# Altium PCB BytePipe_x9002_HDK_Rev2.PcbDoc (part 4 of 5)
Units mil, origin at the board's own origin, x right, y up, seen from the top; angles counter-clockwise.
Board outline 4250 x 4250 mil, 8 copper layers (Top Layer, L2-GND, L3-SIG, L4-GND, L5-PWR, L6-SIG, L7-GND, Bottom Layer), stack 63 mil thick; 296 components, 250 nets, 1198 pads, 2326 vias.
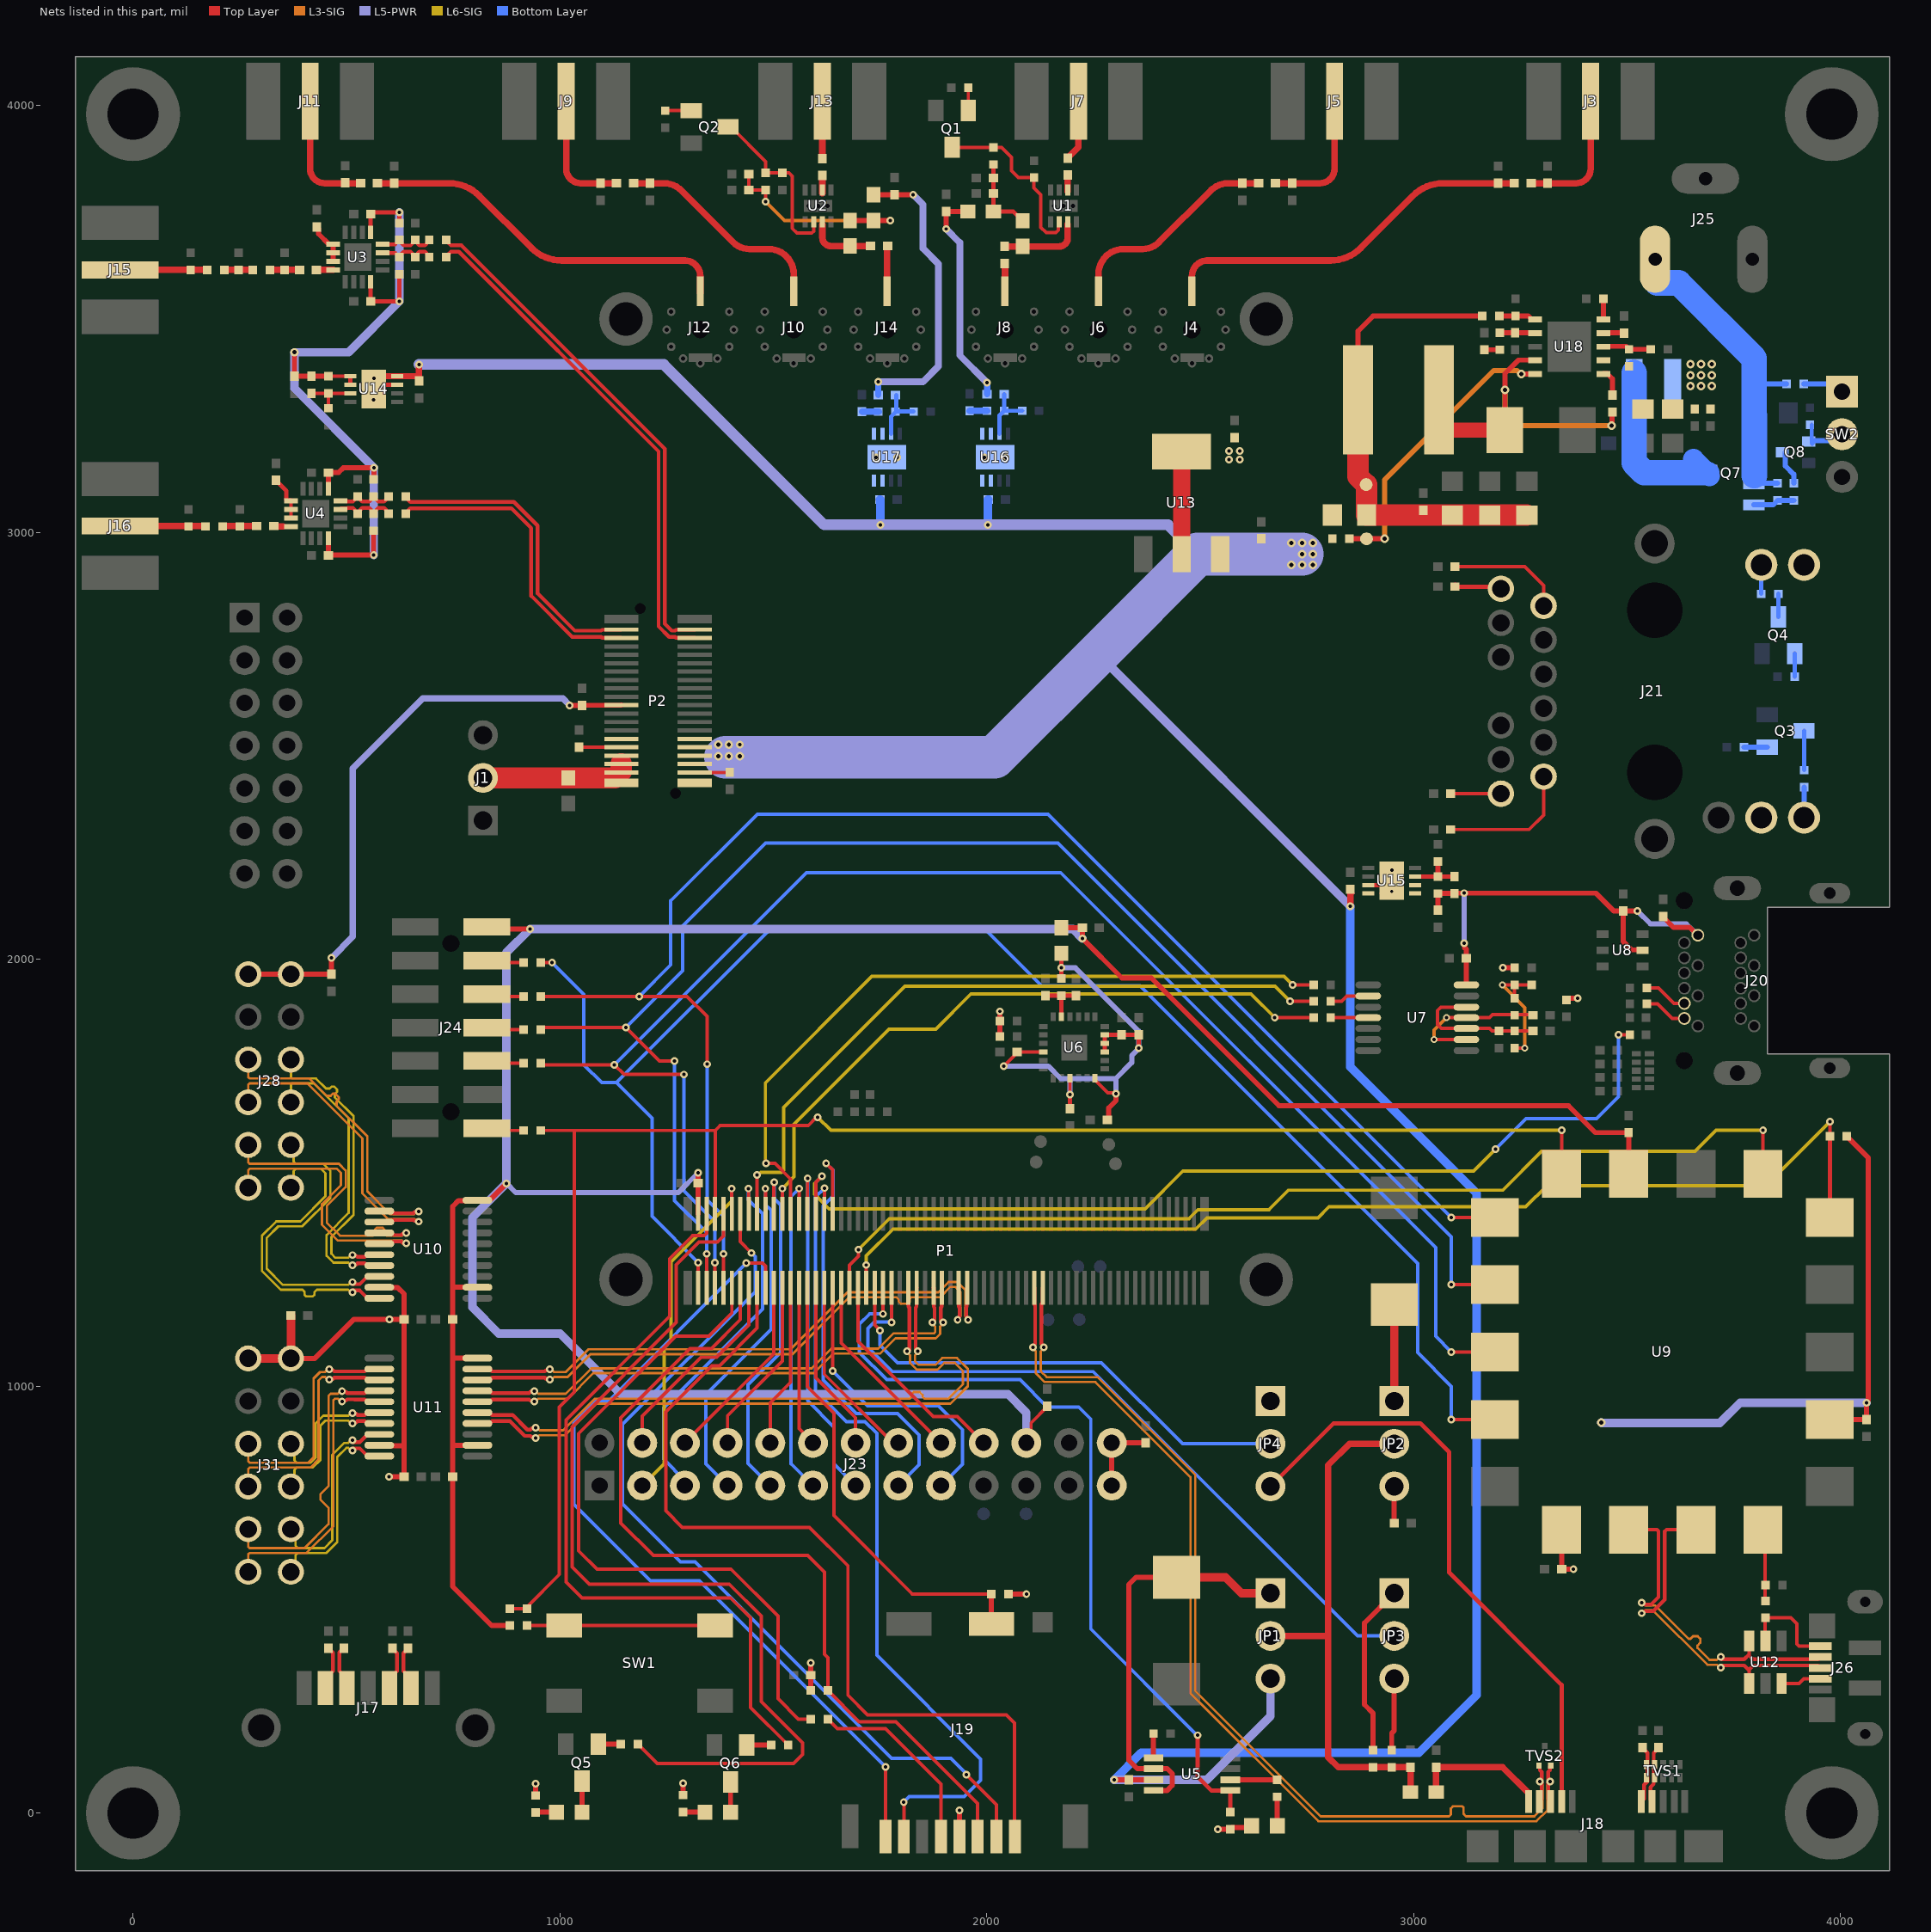
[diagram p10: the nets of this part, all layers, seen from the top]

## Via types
v1: diameter 18, hole 8, Top Layer to Bottom Layer, tented both sides, 2283 vias
v2: diameter 20, hole 10, Top Layer to Bottom Layer, tented both sides, 39 vias
v3: diameter 16, hole 8, Top Layer to Bottom Layer, tented both sides, 4 vias

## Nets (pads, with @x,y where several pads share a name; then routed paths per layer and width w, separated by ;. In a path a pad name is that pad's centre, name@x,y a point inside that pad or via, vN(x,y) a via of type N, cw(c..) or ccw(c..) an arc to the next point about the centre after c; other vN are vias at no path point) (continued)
IO_L10_N: P1.70 U11.5 | length 1574.6
  Top Layer w8.75: U11.5@807,938 835.96,938 841.34,932.62 889.45,932.62 923.86,898.21 931.31,898.21 934.16,901.07 941.45,901.07 v1(943.22,902.84) ; P1.70@1816.42,1230.39 1817.04,1229.76 1817.04,1185.88 1818.88,1184.04 v1@1818.88,1084.9
  L3-SIG w5.5: v1(943.22,902.84) 946.44,902.84 952.69,896.59 964.42,896.59 1007.94,896.59 1081.85,970.51 1819.51,970.51 1823,974 1823,980 1829,986 1843,986 1850,979 1850,975 1854.49,970.51 1910.51,970.51 1944.5,1004.5 1944.5,1035.5 1925.5,1054.5 1900.76,1054.5 1884.76,1038.5 1836.24,1038.5 1820.48,1054.26 1820.48,1072.12 1813.73,1078.87 v1(1813.73,1081.59)
IO_L10_P: P1.68 U11.4 | length 1575.1
  Top Layer w8.75: U11.4@807,912.5 835.96,912.5 841.34,917.88 883.34,917.88 917.75,883.46 931.31,883.46 934.16,880.61 941.45,880.61 v1(943.22,878.84) ; v1@1833.63,1084.76 1833.63,1184.04 1835.48,1185.88 1835.48,1229.76 P1.68@1836.1,1230.39
  L3-SIG w5.5: v1(943.22,878.84) 946.44,878.84 952.69,885.09 969.19,885.09 1012.7,885.09 1086.62,959.01 1915.27,959.01 1956,999.74 1956,1040.26 1930.26,1066 1896,1066 1880,1050 1841,1050 1831.98,1059.02 1831.98,1072.12 1838.73,1078.87 v1(1838.73,1081.59)
IO_L11_N: P1.64 U11.7 | length 1243.7
  Top Layer w8.75: U11.7@807,989 835.96,989 841.34,983.62 856.81,983.62 ; 856.84,983.59 899.8,983.59 ; 899.84,983.56 928.09,983.56 930.94,986.41 938.23,986.41 v1(940,988.18) ; P1.64@1875.47,1230.39 1876.1,1229.76 1876.1,1185.88 1877.94,1184.04 v1@1877.94,1152.1
  L3-SIG w5.5: v1(940,988.18) 943.22,988.18 949.47,981.93 1013.99,981.93 1073.83,1041.77 1590.18,1041.77 1636.4,1088 1745.96,1088 1781.49,1123.53 1876.4,1123.53 1879.62,1126.75 1879.62,1139.51 1872.87,1146.26 v1(1872.87,1148.98)
IO_L11_P: P1.62 U11.6 | length 1262.8
  Top Layer w8.75: U11.6@807,963.5 835.96,963.5 841.34,968.88 850,968.88 850.07,968.81 856.81,968.81 ; 856.84,968.84 893.69,968.84 ; 893.73,968.81 928.09,968.81 930.94,965.95 938.23,965.95 v1(940,964.18) ; v1@1892.69,1152.1 1892.69,1184.04 1894.53,1185.88 1894.53,1229.76 P1.62@1895.16,1230.39
  L3-SIG w5.5: v1(940,964.18) 943.22,964.18 949.47,970.43 1018.75,970.43 1078.6,1030.27 1594.94,1030.27 1641.16,1076.5 1750.73,1076.5 1786.25,1112.03 1881.16,1112.03 1891.12,1121.99 1891.12,1139.51 1897.87,1146.26 v1(1897.87,1148.98)
IO_L12_N: P1.56 U11.9 | length 1395.6
  Top Layer w8.75: U11.9@807,1040 835.96,1040 841.34,1034.63 947.47,1034.63 964.98,1034.61 967.84,1037.47 975.13,1037.47 v1(976.9,1039.24) ; P1.56@1954.21,1230.39 1953.59,1229.76 1953.59,1185.88 1951.75,1184.04 1951.75,1163.04 1956.84,1157.95 v1(1956.84,1155.44)
  L3-SIG w5.5: v1(976.9,1039.24) 980.12,1039.24 986.37,1032.99 1013.55,1032.99 1066.91,1086.35 1540.37,1086.35 1674.01,1220 1886.74,1220 1910.74,1244 1931.26,1244 1950.09,1225.18 1950.09,1164.92 1956.84,1158.17 v1(1956.84,1155.44)
IO_L12_P: P1.58 U11.8 | length 1396.5
  Top Layer w8.75: U11.8@807,1014.5 835.96,1014.5 841.34,1019.88 941.36,1019.88 964.98,1019.86 967.84,1017.01 975.13,1017.01 v1(976.9,1015.24) ; v1(1931.84,1155.44) 1931.84,1157.95 1937,1163.1 1937,1184.04 1935.15,1185.88 1935.15,1229.76 P1.58@1934.53,1230.39
  L3-SIG w5.5: v1(976.9,1015.24) 980.12,1015.24 986.37,1021.49 1018.31,1021.49 1071.68,1074.85 1545.13,1074.85 1678.78,1208.5 1788.5,1208.5 1794,1203 1794,1198 1799,1193 1815,1193 1820,1198 1820,1205 1823.5,1208.5 1891.5,1208.5 1915.5,1232.5 1926.5,1232.5 1938.59,1220.41 1938.59,1164.92 1931.84,1158.17 v1(1931.84,1155.44)
MCS0_N: R6.2 R9.2 R13.1 U3.11 | length 139.4
  Top Layer w8.75: U3.11@585,3655 585.13,3654.87 614.12,3654.87 R6.2@624,3645 629.62,3650.62 629.63,3652.48 634.75,3657.61 650.25,3657.61 655.38,3652.48 655.38,3650.62 R13.1@661,3645 666.62,3650.62 666.62,3653.38 670.88,3657.62 684.12,3657.62 688.38,3653.38 688.38,3650.62 R9.2@694,3645
MCS0_P: R7.2 R8.2 R14.1 U3.12 | length 139.5
  Top Layer w8.75: U3.12@585,3675 U3.12@585,3675 614.12,3675.06 R7.2@624.03,3684.97 629.66,3679.34 629.66,3677.48 634.78,3672.36 650.23,3672.36 655.38,3677.5 655.38,3679.38 R14.1@661,3685 666.62,3679.38 666.62,3676.62 670.88,3672.38 684.12,3672.38 688.38,3676.62 688.38,3679.37 R8.2@694,3685
MCS_N: P2.06 R9.1 | length 1203.9
  Top Layer w8.75: R9.1@734,3645 739.63,3650.62 739.63,3652.5 744.75,3657.62 763.38,3657.62 1231.25,3189.75 1231.25,2779.89 1256.04,2755.11 1270.27,2755.11 1272.11,2753.26 1315.99,2753.26 P2.06@1316.61,2752.64
MCS_P: P2.04 R8.1 | length 1203.9
  Top Layer w8.75: R8.1@734,3685 739.62,3679.38 739.62,3677.5 744.75,3672.38 769.48,3672.38 1246,3195.86 1246,2786 1262.14,2769.86 1270.27,2769.86 1272.11,2771.7 1315.99,2771.7 P2.04@1316.61,2772.32
MIO26: J23.11 P1.95 | length 784
  Top Layer w8: P1.95@1560.44,1403.68 v1@1560.44,1462.93
  Bottom Layer w8: v1(1560.37,1463) 1542,1444.63 1542,818 J23.11@1593,767
MIO27: P1.105 R40.2 | length 1680.1
  Top Layer w8: P1.105@1461.54,1403.07 P1.105@1462.09,1403.61 1462.04,1403.66 1462.04,1494.96 v1(1462,1495) ; v1(2710.94,1902) R40.2@2766,1902
  L6-SIG w8: v1(1462,1495) 1464.71,1495 1470.71,1501 1519.31,1501 1524,1505.69 1524,1653 1808,1937 2675.94,1937 v1(2710.94,1902)
MIO28: P1.91 R49.1 | length 2322
  Top Layer w8: P1.91@1599.88,1403.61 P1.91@1599.88,1403.61 1599.94,1477.94 v1(1614,1492) ; v1(3480.67,1822.92) 3480.75,1823 R49.1@3507,1823
  L6-SIG w8: v1(1614,1492) 1597,1475 1597,1449 1630.7,1415.3 2371.16,1415.3 2459.52,1503.66 3140.9,1503.66 v1(3192.31,1555.07)
  Bottom Layer w8: v1(3192.31,1555.07) 3263.65,1626.41 3429.05,1626.41 3480.67,1678.04 v1(3480.67,1822.92)
MIO29: P1.97 R39.2 | length 1740.1
  Top Layer w8: v1(1483,1522) 1504,1522 1540.83,1485.17 P1.97@1540.83,1403.61 ; v1@2717.12,1939.88 R39.2@2765.88,1939.88
  Top Layer w10: v1(2717,1939.77) v1@2717.12,1939.88 ; R39.2@2765.88,1939.88 R39.2@2766,1940
  L6-SIG w8: v1(1483,1522) 1481.61,1523.39 1481.61,1710.72 1730.88,1960 2696.77,1960 v1(2717,1939.77)
MIO30: P1.99 R42.2 | length 1588.6
  Top Layer w8: v1(1521,1463) 1521.07,1462.93 1521.07,1403.68 P1.99@1521.14,1403.61 ; v1@2675.04,1862.99 R42.2@2766,1863
  L6-SIG w8: v1(1521,1463) 1549,1491 1549,1613.97 1771.52,1836.48 1880.48,1836.48 1963,1919 2619,1919 v1(2675.03,1862.97)
MIO31: J23.5 P1.107 | length 885.6
  Top Layer w8: P1.107@1442.33,1403.68 v1@1442.33,1462.93
  Bottom Layer w8: J23.5@1293,767 1293,779 1243,829 1243,949 1475,1181 1475,1404.04 1442.26,1436.78 v1(1442.26,1463)
MIO32: J23.3 P1.111 | length 842.2
  Top Layer w8: P1.111@1402.96,1403.68 v1@1402.96,1462.93
  L6-SIG w8: J23.3@1193,767 1244,818 1244,1090 1261,1107 1261,1291 1402.89,1432.89 v1(1402.89,1463)
MIO33: J23.13 P1.93 | length 849.9
  Top Layer w8: P1.93@1580.28,1403.7 v1@1580.28,1486.91
  Bottom Layer w8: v1(1580.37,1487) 1580.37,965.63 1642,904 1642,818 J23.13@1693,767
MIO34: J23.6 P1.102 | length 449.7
  Top Layer w8: J23.6@1293,867 1501.34,1075.34 1501.34,1230.27 P1.102@1501.46,1230.39
MIO35: J23.9 P1.101 | length 844.5
  Top Layer w8: P1.101@1501.54,1403.7 v1@1501.54,1478
  Bottom Layer w8: J23.9@1493,767 1441,819 1441,1003 1517,1079 1517,1424 1502,1439 v1(1502,1478)
MIO36: J23.7 P1.103 | length 845.3
  Top Layer w8: P1.103@1481.7,1403.68 v1@1481.7,1462.93
  Bottom Layer w8: J23.7@1393,767 1342,818 1342,980 1495,1133 1495,1412.21 1481.63,1425.58 v1(1481.63,1463)
MIO37: J23.15 P1.87 | length 1066.7
  Top Layer w8: v1(1623.65,1522.39) 1639.1,1506.93 1639.1,1403.76 P1.87@1639.25,1403.61
  Bottom Layer w8: v1(1623.65,1522.39) 1640,1506.03 1640,1445 1617,1422 1617,1014 1695,936 1791,936 1842,885 1842,816 J23.15@1793,767
MIO38: J23.17 P1.88 | length 708.1
  Top Layer w8: v1(1638.95,1035.44) 1639.67,1036.15 1639.67,1229.97 P1.88@1639.25,1230.39
  Bottom Layer w8: v1(1638.95,1035.44) 1720.39,954 1887,954 1943,898 1943,817 J23.17@1893,767
MIO39: J23.14 P1.92 | length 402
  Top Layer w8: P1.92@1599.88,1230.39 1600,1230.27 1600,1019.2 1693,926.2 J23.14@1693,867
MIO40: J23.10 P1.98 | length 383.2
  Top Layer w8: J23.10@1493,867 1493,961 1540.83,1008.83 P1.98@1540.83,1230.39
MIO41: J23.16 P1.90 | length 442.5
  Top Layer w8: P1.90@1619.57,1230.39 1619.57,1027.95 1780.52,867 J23.16@1793,867
MIO42: J23.8 P1.100 | length 416.5
  Top Layer w8: J23.8@1393,867 1393,930.32 1521.14,1058.46 P1.100@1521.14,1230.39
MIO43: J23.4 P1.108 | length 487.7
  Top Layer w8: J23.4@1193,867 1193,929.88 1331.12,1068 1367,1068 1442.4,1143.4 P1.108@1442.4,1230.39
MIO44: J23.12 P1.96 | length 394.9
  Top Layer w8: P1.96@1560.51,1230.39 1560.51,900.98 1593,868.49 J23.12@1593,867
  Bottom Layer w8: J23.12@1582,880.47 1593,869.47 J23.12@1593,867
MIO45: J19.9 P1.94 R35.2 | length 1080.2
  Top Layer w8: P1.94@1580.2,1230.39 1580.2,998.8 1642,937 1642,697 1826.01,512.99 1978.2,512.99 R35.2@2011,513
  Top Layer w12: J19.9@2011,437 R35.2@2011,513
MIO46: J19.7 P1.89 | length 1930.2
  Top Layer w8: P1.89@1619.57,1403.61 1619.78,1403.83 1619.78,1463.78 v1(1620,1464) ; v1(1805.85,25.17) 1806,25.01 J19.7@1806,-55 J19.7@1806,-61
  Bottom Layer w8: v1(1620,1464) 1599,1443 1599,989 1671,917 1715,917 1742.65,889.35 1742.65,369.35 1986,126 1986,77 1947,38 1818.68,38 v1(1805.85,25.17)
MIO47: J19.8 P1.104 | length 2003.9
  Top Layer w8: v1(1437,1288) 1474.81,1288 1481.77,1281.04 P1.104@1481.77,1230.39 P1.104@1481.89,1230.27 ; J19.8@1763,-61 J19.8@1763,-55 v1(1763,108)
  Bottom Layer w8: v1(1437,1288) 1114.5,965.5 1081.5,965.5 1033,917 1033,723 1212,544 1327,544 v1(1763,108)
MIO48: J19.1 P1.106 | length 2094.4
  Top Layer w8: P1.106@1462.04,1230.34 1462.09,1230.3 1462.09,1136.09 1374,1048 1356,1048 1248,940 1248,708 1287,669 1585,669 1675,579 1675,276 1721,230 2046,230 2065,211 2065,-60 J19.1@2066,-61
MIO49: J19.2 P1.109 | length 2065.8
  Top Layer w8: P1.109@1422.72,1403.61 1422.72,1338.48 v1(1449.22,1311.97) ; v1(1952.5,89.5) 2023,19 J19.2@2023,-55
  Bottom Layer w8: v1(1449.22,1311.97) 1457.52,1303.67 1457.52,1221.02 1147,910.5 1147,724 1283,588 1317,588 1777,128 1916,128 1952.5,91.5 v1(1952.5,89.5)
MIO50: J19.3 P1.110 R36.2 | length 2039.4
  Top Layer w8: P1.110@1422.72,1230.39 1422.86,1230.24 1422.86,1155.86 1355,1088 1305,1088 1143,926 1143,679 1219,603 1581,603 1620,564 1620,372 1628,364 R36.2@1628,287 1701,214 1787,214 1979,22 J19.3@1979,-55
MIO51: P1.112 R37.2 | length 1631.9
  Top Layer w8: P1.112@1402.03,1229.39 P1.112@1403.03,1230.39 1403.03,1171.03 1349,1117 1272,1117 1043.98,888.98 1043.98,614.02 1087,571 1401,571 1511,461 1511,267.96 1558.96,220 R37.2@1588,220
NetC6_1: C6.1 C7.1 L1.2 L4.2 R1.1 | length 187.1
  Top Layer w10: R1.1@2016,3862 L1.2@2016,3752 2062,3752 L4.2@2084,3730
NetC8_1: C8.1 J3.1 L2.1 | length 316.4
  Top Layer w15.35: L2.1@3276,3818 C8.1@3314,3818 3381,3818 ccw(c3381,3852) 3415,3852 J3.1@3415,4010
NetC9_1: C9.1 J4.1 L2.2 | length 882.2
  Top Layer w15.35: J4.1@2481,3561 2481,3600 ; 2480.97,3600.5 cw(c2517.5,3600.5) 2517.5,3637.03 ; 2516.5,3637 2805.58,3637 ccw(c2805.58,3737) 2876.29,3666.29 2998.71,3788.71 cw(c3069.42,3718) 3069.42,3818 C9.1@3198,3818 L2.2@3236,3818
NetC10_1: C10.1 J5.1 L3.1 | length 315.4
  Top Layer w15.35: L3.1@2677,3818 C10.1@2716,3818 2781,3818 ccw(c2781,3852) 2815,3852 J5.1@2815,4010
NetC11_1: C11.1 J6.1 L3.2 | length 512.7
  Top Layer w15.35: J6.1@2262,3561 2262,3605 cw(c2321,3605) 2321,3664 ; 2320,3664 2366,3664 ccw(c2366,3717.11) 2403.55,3679.55 2525,3801 cw(c2566.04,3759.96) 2566.04,3818 L3.2@2637,3818
NetC12_1: C12.1 J7.1 | length 155.4
  Top Layer w15.35: C12.1@2190,3877 2215,3902 J7.1@2215,4010 J7.1@2215,4022
NetC12_2: C12.2 U1.2 | length 38
  Top Layer w15.35: U1.2@2190,3799 C12.2@2190,3837
NetC13_1: C13.1 L4.1 U1.7 | length 191.4
  Top Layer w15: C13.1@2042,3670 2170,3670 ; 2190,3690 U1.7@2190,3722
  Top Layer w15.35: 2170,3670 ccw(c2170,3690) 2190,3690
NetC13_2: C13.2 J8.1 | length 69
  Top Layer w15.35: J8.1@2043,3561 C13.2@2043,3630
NetC14_1: C14.1 J9.1 L5.1 | length 295.4
  Top Layer w15.35: J9.1@1015,4010 1015,3852 ccw(c1049,3852) 1049,3818 L5.1@1133,3818
NetC15_1: C15.1 J10.1 L5.2 | length 512.7
  Top Layer w15.35: L5.2@1173,3818 C15.1@1211,3818 1243.96,3818 cw(c1243.96,3759.96) 1285,3801 1406.45,3679.55 ccw(c1444,3717.11) 1444,3664 1490,3664 ; 1489,3664 cw(c1489,3605) 1548,3605 J10.1@1548,3561
NetC16_1: C16.1 J11.1 L6.1 | length 295.4
  Top Layer w15.35: J11.1@415,4010 415,3852 ccw(c449,3852) 449,3818 495,3818 L6.1@533,3818
NetC17_1: C17.1 J12.1 L6.2 | length 883.2
  Top Layer w15.35: L6.2@573,3818 740.58,3818 cw(c740.58,3718) 811.29,3788.71 933.71,3666.29 ccw(c1004.42,3737) 1004.42,3637 1293.5,3637 ; 1292.5,3637.03 cw(c1292.5,3600.5) 1329.03,3600.5 ; J12.1@1329,3561 1329,3600
NetC19_1: C19.1 C20.1 L7.2 L8.2 R4.1 | length 506.2
  Top Layer w8: C20.1@1443,3839 C19.1@1443,3802 R4.1@1482,3802 v1@1482,3776
  Top Layer w12: L8.2@1680,3731 L7.2@1735,3731 v1(1774,3731)
  L3-SIG w8: v1(1482,3775) 1526,3731 v1(1774,3731)
NetC21_1: C21.1 J13.1 | length 134
  Top Layer w15.35: C21.1@1615,3876 J13.1@1615,4010
NetC21_2: C21.2 U2.2 | length 41
  Top Layer w15.35: U2.2@1615,3795 C21.2@1615,3836
NetC22_1: C22.1 L8.1 U2.7 | length 154.7
  Top Layer w15.35: U2.7@1615,3721 1615,3691 ccw(c1635,3691) 1635,3671 L8.1@1680,3671 C22.1@1728,3671 C22.1@1728.31,3671
NetC22_2: C22.2 J14.1 | length 110
  Top Layer w15.35: J14.1@1767,3561 C22.2@1767,3671
NetC25_1: C25.1 R12.1 R17.1 | length 69
  Top Layer w15.35: R12.1@321,3615 R17.1@355,3615 C25.1@390,3615
NetC25_2: C25.2 U3.4 | length 39
  Top Layer w15.35: C25.2@430,3615 U3.4@469,3615
NetC26_1: C26.1 U3.1 U3.2 U3.3 | length 102.6
  Top Layer w12: C26.1@430.55,3715.87 434.55,3711.87 434.55,3699.45 459,3675 U3.1@469,3675 U3.2@469,3655 U3.3@469,3635
NetC29_1: C29.1 R22.1 R26.1 | length 80
  Top Layer w15.35: R22.1@210.04,3014.81 250.04,3014.81 C29.1@290.04,3014.81
NetC29_2: C29.2 U4.4 | length 21.4
  Top Layer w12: C29.2@330,3015 C29.2@331,3014
  Top Layer w15.35: C29.2@331,3014 351,3014
NetC30_1: C30.1 U4.1 U4.2 U4.3 | length 107.8
  Top Layer w8: U4.3@370.04,3034.81 370.04,3054.81 U4.1@370.04,3074.81
  Top Layer w10: C30.1@335.19,3122.34 335.19,3121.34 359.04,3097.49 359.04,3075.81 360.04,3074.81 U4.1@370.04,3074.81
NetC36_1: C36.1 JP1.1 U5.6 U5.8 | length 956.6
  Top Layer w12: U5.8@2391,53 2423,53 2435,65 2435,92 2423,104 U5.6@2391,104 2353,104 2333,124 2333,535 2350,552 C36.1@2445,552
  Top Layer w20: C36.1@2445,552 2560,552 2597,515 JP1.1@2665,515
NetC37_1: C37.1 JP2.1 | length 226
  Top Layer w20: JP2.1@2955,965 C37.1@2955,1191
NetC38_1: C38.1 JP2.3 | length 86
  Top Layer w12: C38.1@2955,679 JP2.3@2955,765
NetC40_1: C40.1 J18.1 L9.2 | length 319.3
  Top Layer w12: J18.1@3270,27 J18.1@3270,46
  Top Layer w15: L9.2@3053,49 C40.1@3053,107 3209,107 J18.1@3270,46
NetC44_1: C44.1 C45.1 C46.1 C47.1 C50.1 L10.2 R32.1 U6.10 U6.15 U6.18 U6.21 U6.22 U6.23 | length 1247.3
  Top Layer w8: v1(2040,1750) 2072,1782 C50.1@2071,1783 U6.10@2133,1783 ; v1(2195,1683) U6.15@2195,1721 ; U6.18@2254,1721 2254,1717 2284.09,1686.91 2301.09,1686.91 v1(2303,1685)
  Top Layer w10: R32.1@2175,1955 v1(2175,1980) L10.2@2175,2014 ; C46.1@2195,1650 v1(2195,1683) ; U6.21@2277,1783 U6.22@2277,1803 U6.23@2277,1823 C44.1@2356,1823 v1(2356,1792)
  Top Layer w12: C45.1@2282.92,1623.47 2285.75,1626.3 2285.75,1651.47 2303,1668.72 v1(2303,1685)
  L5-PWR w12: v1(2040,1750) 2144,1750 2174,1720 2302,1720 ; v1(2175,1980) 2208,1980 2356,1832 v1(2356,1792) 2356,1790.38 2340,1774.38 2340,1758 2302,1720 ; v1(2195,1683) 2195,1719 ; v1(2303,1685) 2303,1719 2302,1720
NetC48_1: C48.1 C49.1 R32.2 U6.5 | length 121
  Top Layer w10: C48.1@2138,1915 R32.2@2175,1915 ; U6.5@2175,1865 R32.2@2175,1915 ; C49.1@2209,1915 R32.2@2175,1915
NetC58_1: C58.1 R38.2 R44.1 U7.10 U7.12 | length 334.5
  Top Layer w8: U7.12@3124,1888 3064,1888 3056,1880 3056,1847 3065,1838 U7.10@3124,1838 3178,1838 3184,1832 R38.2@3200,1832 C58.1@3280,1832
NetC59_1: C59.1 R43.1 U7.9 U7.11 | length 345.3
  Top Layer w8: v3(3048,1812) U7.9@3124,1812 ; v3(3077,1863) U7.11@3124,1863 3178,1863 3185,1870 3279,1870 C59.1@3280,1869
  L3-SIG w8: v3(3048,1812) 3048,1834 v3(3077,1863)
NetC61_2: C61.2 J21.12 | length 118
  Top Layer w8: C61.2@3087,2388 J21.12@3205,2388
NetC62_2: C62.2 J21.6 | length 322.1
  Top Layer w8: C62.2@3087,2304 3271,2304 3305,2338 J21.6@3305,2428
NetC63_2: C63.2 J21.1 | length 274.2
  Top Layer w8: C63.2@3097,2920 3261,2920 3305,2876 J21.1@3305,2828
NetC64_2: C64.2 J21.7 | length 111.1
  Top Layer w10: C64.2@3098,2878 3103,2873 3200,2873 J21.7@3205,2868
NetC73_2: C73.2 C74.2 C92.1 C93.1 L11.2 R79.2 U18.2
  other v2: 3649,3343 3674,3343 3699,3343 3649,3368 3674,3368 3699,3368 3649,3394 3674,3394 3699,3394
NetC81_2: C81.2 R66.1 R67.2 U14.3 | length 126
  Top Layer w8: C81.2@418,3326 R66.1@458,3326 ; R67.2@458,3291 R66.1@458,3326 ; U14.3@509,3326 R66.1@458,3326
NetC84_2: C84.2 R71.1 R72.2 U15.3 | length 131
  Top Layer w10: U15.3@3004,2194 R71.1@3057,2194 C84.2@3100,2194
  Top Layer w12: R71.1@3057,2194 R72.2@3057,2229
NetC87_2: C87.2 R73.1 R74.2 U16.3 | length 139.6
  Bottom Layer w10: U16.3@2030,3231 2030,3274 R73.1@2041,3285 ; C87.2@2041,3324 R73.1@2041,3285 ; R74.2@2083,3285 R73.1@2041,3285
NetC90_2: C90.2 R75.1 R76.2 U17.3 | length 137
  Bottom Layer w10: U17.3@1776,3231 1776,3271 R75.1@1788,3283 ; C90.2@1788,3322 R75.1@1788,3283 ; R76.2@1829,3283 R75.1@1788,3283
NetC94_1: C94.1 J25.1 Q7.1 Q7.2 Q7.3 R78.1 R84.1 | length 756.2
  Bottom Layer w12: Q7.3@3797.56,3115 R78.1@3853,3115 ; 3798,3348 R84.1@3874,3348
  Bottom Layer w50: J25.1@3566,3630 3566,3615.32 J25.1@3575.7,3605.61 ; C94.1@3798,3275 C94.1@3798.53,3274.47
  Bottom Layer w60: J25.1@3571.08,3605.61 3571.08,3584.51 3621.49,3584.51 3798,3408 3798,3348 C94.1@3798,3280 C94.1@3798,3275 ; 3798.53,3133 3798.53,3165 3798.53,3215 C94.1@3798.53,3274.47
NetC95_1: C95.1 L11.1 Q7.5 | length 448.7
  Bottom Layer w50: 3656,3170.38 Q7.5@3686.38,3140 ; Q7.5@3680.91,3140 Q7.5@3686.38,3140 ; Q7.5@3692.44,3140 Q7.5@3686.38,3140 ; Q7.5@3693.41,3132.97 Q7.5@3686.38,3140
  Bottom Layer w60: L11.1@3517,3374 L11.1@3517,3339 C95.1@3517,3209 3517,3163.28 3540.28,3140 Q7.5@3680.91,3140
NetC96_1: C96.1 U18.1 | length 64
  Top Layer w12: U18.1@3445,3372 3454,3372 3466,3360 C96.1@3466,3322
NetC96_2: C96.2 D1.1 L12.1 U18.9 | length 827.7
  Top Layer w12: L12.1@3080,3269 L12.1@3080,3311 ; D1.1@3214,3240 3214.3,3240.3 v2(3214.3,3333.62) 3214.3,3372.3 3245.77,3403.77 U18.9@3284.77,3403.77 ; v2(3464,3250) 3465,3251 3465,3281 C96.2@3466,3282 C96.2@3466,3281
  Top Layer w35: L12.1@3060,3311 3060,3257.5 3077.5,3240 D1.1@3214,3240
  L3-SIG w12: v2(3214.3,3333.62) 3214.3,3270.7 3235,3250 v2(3464,3250)
NetC97_2: C97.2 C98.1 C99.1 C100.1 L12.2 R81.1 R82.2 TP12.1 | length 1120.6
  Top Layer w12: L12.2@2870,3311 2870,3471.65 2905.35,3507 R82.2@3161,3507
  Top Layer w25: C100.1@3265,3041 C100.1@3266,3040
  Top Layer w50: L12.2@2870,3311 2870,3131 TP12.1@2889,3112 ; TP12.1@2890,3112 R81.1@2890,3041 C100.1@3265,3041
NetC101_2: C101.2 U18.4 | length 49
  Top Layer w12: U18.4@3445,3468 C101.2@3494,3468
NetC102_2: C102.2 R87.2 U18.7 | length 83
  Top Layer w12: R87.2@3202,3468 U18.7@3285,3468
NetC103_1: C103.1 R87.1 | length 36
  Top Layer w12: C103.1@3166,3428 R87.1@3202,3428
NetJ15_1: J15.1 R10.2 R15.1 | length 204
  Top Layer w15.35: J15.1@-30,3615 R15.1@135,3615 R10.2@174,3615
NetJ16_1: J16.1 R22.2 R25.1 | length 200
  Top Layer w15.35: J16.1@-29.96,3014.81 130.04,3014.81 R22.2@170.04,3014.81
NetJ19_5: J19.5 R37.1 | length 457
  Top Layer w8: R37.1@1628,220 1650,198 1763,198 1893,68 J19.5@1893,-55 J19.5@1893,-61
NetJ20_4: J20.4 R45.1 | length 102
  Top Layer w8: R45.1@3547,1896 3572,1896 3606.58,1861.42 J20.4@3634.72,1861.42
NetJ20_6: J20.6 R46.1 | length 102.7
  Top Layer w8: R46.1@3547,1933 3574,1933 3610.15,1896.85 J20.6@3634.72,1896.85
NetJ21_13: J21.13 R53.2 | length 68
  Bottom Layer w10: R53.2@3815,2856 J21.13@3815,2924
NetJ21_17: J21.17 R51.2 | length 73.8
  Top Layer w12: J21.17@3913,2330 J21.17@3915,2332
  Bottom Layer w12: J21.17@3915,2332 R51.2@3915,2403
NetJ24_4: J24.4 R55.2 | length 86
  Top Layer w8: J24.4@829,1992 R55.2@915,1992
NetJ24_6: J24.6 R56.2 | length 86
  Top Layer w8: J24.6@829,1913 R56.2@915,1913
NetJ24_8: J24.8 R57.2 | length 86
  Top Layer w8: J24.8@829,1835 R57.2@915,1835
NetJ24_10: J24.10 R58.2 | length 86
  Top Layer w8: J24.10@829,1757 R58.2@915,1757
NetJ24_14: J24.14 R59.2 | length 86
  Top Layer w8: J24.14@829,1599 R59.2@915,1599
NetJ26_1: J26.1 R62.1 U12.2 | length 237.9
  Top Layer w8: U12.2@3824,403.06 3824,457 3884,457 3898,443 3898,396 3903,391 J26.1@3953,391
NetJ26_4: J26.4 U12.6 | length 95.5
  Top Layer w8: U12.6@3862.03,303.03 3903.03,303.03 3914,314 J26.4@3953,314
NetJP3_1: JP3.1 R27.2 | length 405.3
  Top Layer w12: R27.2@2905,147 2905,234 2885,254 2885,445 JP3.1@2955,515
NetJP3_3: JP3.3 R28.1 | length 170.5
  Top Layer w12: R28.1@2949,147 2949,187 2955,193 JP3.3@2955,315
NetLED1_1: LED1.1 R30.1 | length 68
  Top Layer w12: LED1.1@2681,-30 R30.1@2681,38
NetLED2_1: LED2.1 Q5.3 | length 73
  Top Layer w12: LED2.1@1052,2 Q5.3@1052,75
NetLED2_2: LED2.2 R65.2 | length 49
  Top Layer w12: R65.2@943,2 LED2.2@992,2
NetLED3_1: LED3.1 Q6.3 | length 71
  Top Layer w12: LED3.1@1400,2 Q6.3@1400,73
NetLED3_2: LED3.2 R69.2 | length 51
  Top Layer w12: R69.2@1289,2 LED3.2@1340,2
NetQ1_1: Q1.1 R3.2 | length 53.7
  Top Layer w8: Q1.1@1957,3988.31 R3.2@1957,4042
NetQ1_3: Q1.3 R1.2 R2.2 U1.6 | length 432.3
  Top Layer w8: Q1.3@1918.86,3902.17 1919.03,3902 R1.2@2016,3902 2035,3902 2058,3879 2058,3847.76 2074.76,3831 R2.2@2111,3831 2111,3807 2127,3791 2127,3714.86 2139.86,3702 2162,3702 2168,3708 2168,3726 U1.6@2170,3728
NetQ2_1: Q2.1 R11.2 | length 61
  Top Layer w8: R11.2@1247,3988 Q2.1@1308,3988
NetQ2_3: Q2.3 R4.2 R5.2 U2.6 | length 408.7
  Top Layer w8: Q2.3@1394,3950 1401,3950 1482,3869 R4.2@1482,3842 R5.2@1521,3842 1537,3842 1545,3834 1545,3712 1556,3701 1590.31,3701 1595,3705.69 U2.6@1595,3721
NetQ3_1: Q3.1 R52.1 | length 55
  Bottom Layer w12: R52.1@3774,2497 Q3.1@3829,2497
NetQ3_3: Q3.3 R51.1 | length 92
  Bottom Layer w10: R51.1@3915,2443 Q3.3@3915,2535
NetQ4_1: Q4.1 R54.1 | length 54
  Bottom Layer w10: R54.1@3893,2662 Q4.1@3893,2716
NetQ4_3: Q4.3 R53.1 | length 54
  Bottom Layer w10: Q4.3@3855,2802 R53.1@3855,2856
NetQ5_1: Q5.1 R68.1 | length 53
  Top Layer w12: Q5.1@1090,161 R68.1@1143,161
NetQ6_1: Q6.1 R70.1 | length 57
  Top Layer w12: Q6.1@1438,159 R70.1@1495,159
NetQ7_4: Q7.4 R78.2 R83.1 | length 97.6
  Bottom Layer w12: Q7.4@3797.56,3065 3837,3065 3843,3065 R78.2@3853,3075 R83.1@3891,3075
NetQ8_1: Q8.1 R88.1 SW2.2 | length 115.3
  Bottom Layer w10: Q8.1@3933,3213 R88.1@3933,3252
  Bottom Layer w12: Q8.1@3933.97,3208.97 3939.97,3214.97 3994.97,3214.97 SW2.2@4004,3224
NetQ8_3: Q8.3 R83.2 | length 81.3
  Bottom Layer w12: Q8.3@3871,3188 3871,3156 3891,3136 R83.2@3891,3115
NetR10_1: R10.1 R12.2 R16.1 | length 67
  Top Layer w15.35: R10.1@214,3615 R16.1@247,3615 R12.2@281,3615
NetR30_2: R30.2 U5.2 | length 110
  Top Layer w12: U5.2@2571,78 R30.2@2681,78
NetR31_1: R31.1 U5.5 | length 57
  Top Layer w12: U5.5@2391,129 R31.1@2391,186
NetR40_1: R40.1 U7.2 | length 93
  Top Layer w8: R40.1@2806,1902 2832,1902 2844,1914 U7.2@2894,1914
NetR42_1: R42.1 U7.4 | length 88
  Top Layer w8: R42.1@2806,1863 U7.4@2894,1863
NetR43_2: R43.2 R44.2 R47.2 R48.2 | length 293
  Top Layer w8: v3@3209,1940 R48.2@3237,1940 ; R44.2@3237,1792 v3(3261,1792) ; R43.2@3237,1909 R48.2@3237,1940 ; R47.2@3277,1940 R48.2@3237,1940
  L3-SIG w8: v3(3208,1940) 3261,1887 v3(3261,1792)
NetR61_1: R61.1 SW1.1 SW1.2 | length 423
  Top Layer w8: R61.1@923,439 SW1.2@992,439 ; SW1.2@1010,439 SW1.1@1364,439
NetR62_2: R62.2 R64.1 U9.18 | length 181
  Top Layer w8: R62.2@3824,497 3824,534 3824,663 U9.18@3839,663
NetR77_2: R77.2 TP11.1 U18.10 | length 681.8
  Top Layer w12: R77.2@2850,2985 TP11.1@2889.97,2985.03 ; TP11.1@2889.97,2985.03 v2@2931.97,2985.03 ; v2@3253.73,3371.27 3254,3371 U18.10@3285,3371
  L3-SIG w12: v2(2932,2985) 2932,3123 3188.03,3379.03 3242.8,3379.03 3250.84,3371 v2(3253,3371)
NetR79_1: R79.1 R80.2 U18.3 | length 113.9
  Top Layer w12: U18.3@3445,3436 3498,3436 R79.1@3505,3429 R80.2@3556,3429
NetR82_1: R82.1 R86.1 U18.6 | length 86.9
  Top Layer w12: R82.1@3201,3507 R86.1@3239,3507 3269,3507 3276,3500 U18.6@3285,3500
NetR84_2: R84.2 SW2.1 | length 99.9
  Bottom Layer w12: R84.2@3914,3348 3980,3348 SW2.1@4004,3324
NetR85_1: R85.1 U18.5 | length 47
  Top Layer w12: U18.5@3445,3500 R85.1@3445,3547
PMOD_A0_N: J28.2 U10.18 | length 748.4
  Top Layer w8.75: v1@515.24,1238.87 531.39,1238.87 549.51,1257 U10.18@577,1257
  L6-SIG w5.5: J28.2@370,1565 376.08,1558.92 376.08,1526.24 381.57,1520.75 445.51,1520.75 462.5,1503.76 462.5,1440.2 396.78,1374.48 340.48,1374.48 313.5,1347.5 313.5,1274.76 350.98,1237.29 504.39,1237.29 510.64,1243.54 v1(513.86,1243.54)
PMOD_A0_P: J28.1 U10.20 | length 769
  Top Layer w8.75: v1@515.24,1224.12 531.39,1224.12 549.51,1206 U10.20@577,1206
  L6-SIG w5.5: J28.1@370,1465 376.08,1471.08 376.08,1503.76 381.57,1509.25 440.75,1509.25 451,1499 451,1444.96 392.02,1385.98 335.72,1385.98 302,1352.26 302,1270 346.21,1225.79 397,1225.79 402,1220.79 402,1214 406,1210 421,1210 425,1214 425,1220 430.79,1225.79 504.39,1225.79 510.64,1219.54 v1(513.86,1219.54)
PMOD_A1_N: J28.4 U10.16 | length 714.2
  Top Layer w8.75: v1(514,1307) 515.77,1305.23 523.06,1305.23 525.66,1302.62 542.66,1302.62 548.04,1308 U10.16@577,1308
  L6-SIG w5.5: J28.4@370,1765 370,1723.97 373.22,1720.75 428.51,1720.75 452.26,1697 461,1697 466,1702 471,1702 478,1695 478,1689 473,1684 473,1676.26 516.78,1632.48 516.78,1401.14 465,1349.35 465,1310.07 474.32,1300.75 504.53,1300.75 510.78,1307 v1(514,1307)
PMOD_A1_P: J28.3 U10.17 | length 692.3
  Top Layer w8.75: v1(514,1283) 515.77,1284.77 523.06,1284.77 526.16,1287.88 542.66,1287.88 548.04,1282.5 U10.17@577,1282.5
  L6-SIG w5.5: J28.3@370,1665 370,1706.03 373.22,1709.25 423.75,1709.25 505.28,1627.72 505.28,1405.9 453.5,1354.12 453.5,1305.3 469.56,1289.25 504.53,1289.25 510.78,1283 v1(514,1283)
PMOD_A2_N: J28.8 U10.14 | length 711.4
  Top Layer w8.75: U10.14@577,1359 605.96,1359 611.34,1353.62 627.84,1353.62 630.94,1356.73 638.23,1356.73 v1(640,1358.5)
  L3-SIG w5.5: J28.8@270,1565 270,1523.97 273.22,1520.75 482.51,1520.75 498.5,1504.76 498.5,1466.24 454.13,1421.87 454.13,1383.13 484.76,1352.5 561.5,1352.5 567,1358 567,1367 571,1371 585,1371 590,1366 590,1357.5 595,1352.5 630.78,1352.5 636.78,1358.5 v1(640,1358.5)
PMOD_A2_P: J28.7 U10.15 | length 685.8
  Top Layer w8.75: U10.15@577,1333.5 605.96,1333.5 611.34,1338.87 628.34,1338.87 630.94,1336.27 638.23,1336.27 v1(640,1334.5)
  L3-SIG w5.5: J28.7@270,1465 270,1506.03 273.22,1509.25 477.75,1509.25 487,1500 487,1471 442.63,1426.63 442.63,1378.37 480,1341 630.28,1341 636.78,1334.5 v1(640,1334.5)
PMOD_A3_N: J28.10 U10.12 | length 769.9
  Top Layer w8.75: U10.12@577,1410 605.96,1410 611.34,1404.62 656.8,1404.62 659.9,1407.73 667.19,1407.73 v1(668.96,1409.5)
  L3-SIG w5.5: J28.10@270,1765 270,1723.97 273.22,1720.75 413.51,1720.75 454.13,1680.13 463.13,1680.13 468,1685 474,1685 482,1677 482,1672 477,1667 477,1657.26 548.98,1585.29 548.98,1456.29 602.01,1403.25 659.49,1403.25 665.74,1409.5 v1(668.96,1409.5)
PMOD_A3_P: J28.9 U10.13 | length 747
  Top Layer w8.75: U10.13@577,1384.5 605.96,1384.5 611.34,1389.88 657.3,1389.88 659.9,1387.27 667.19,1387.27 v1(668.96,1385.5)
  L3-SIG w5.5: J28.9@270,1665 270,1706.03 273.22,1709.25 408.75,1709.25 537.48,1580.52 537.48,1451.52 597.25,1391.75 659.49,1391.75 665.74,1385.5 v1(668.96,1385.5)
PMOD_B0_N: J31.2 U11.18 | length 469.7
  Top Layer w8.75: v1@515.24,868.87 531.39,868.87 549.51,887 U11.18@577,887
  L6-SIG w5.5: J31.2@370,665 380.61,654.39 380.61,626.24 386.1,620.75 448.49,620.75 466.92,639.18 466.92,838.93 495.07,867.08 504.18,867.08 510.64,873.54 v1(513.86,873.54)
PMOD_B0_P: J31.1 U11.20 | length 469.5
  Top Layer w8.75: v1@515.24,854.12 531.39,854.12 549.51,836 U11.20@577,836
  L6-SIG w5.5: J31.1@370,565 380.61,575.61 380.61,603.76 386.1,609.25 453.25,609.25 478.42,634.42 478.42,834.17 499.83,855.58 504.43,855.58 510.48,849.54 v1(513.86,849.54)
PMOD_B1_N: J31.4 U11.16 | length 342.5
  Top Layer w8.75: v1(514,937) 515.77,935.23 523.06,935.23 525.66,932.62 542.66,932.62 548.04,938 U11.16@577,938
  L6-SIG w5.5: J31.4@370,865 378.23,856.77 378.23,826.24 383.72,820.75 416.15,820.75 427.76,832.37 427.76,912.71 445.8,930.75 504.53,930.75 510.78,937 v1(514,937)
PMOD_B1_P: J31.3 U11.17 | length 342.7
  Top Layer w8.75: v1(514,913) 515.77,914.77 523.06,914.77 526.16,917.88 542.66,917.88 548.04,912.5 U11.17@577,912.5
  L6-SIG w5.5: J31.3@370,765 378.23,773.23 378.23,803.76 383.72,809.25 420.91,809.25 439.26,827.6 439.26,907.95 450.56,919.25 504.53,919.25 510.78,913 v1(514,913)
PMOD_B2_N: J31.8 U11.14 | length 697.5
  Top Layer w8.75: v1(489.62,988.37) 491.39,986.6 498.68,986.6 501.54,983.74 525.15,983.74 525.26,983.62 542.66,983.62 548.04,989 U11.14@577,989
  L3-SIG w5.5: J31.8@270,665 270,623.97 273.22,620.75 401.9,620.75 458.12,676.96 458.12,714.88 439,734 439,746.88 458.12,766 458.12,977.12 463.12,982.12 480.15,982.12 486.4,988.37 v1(489.62,988.37)
PMOD_B2_P: J31.7 U11.15 | length 678.7
  Top Layer w8.75: v1(489.62,964.37) 491.39,966.14 498.68,966.14 501.54,968.99 519.04,968.99 519.15,968.87 542.66,968.87 548.04,963.5 U11.15@577,963.5
  L3-SIG w5.5: J31.7@270,565 270,606.03 273.22,609.25 406.67,609.25 469.62,672.2 469.62,967.4 472.84,970.62 480.15,970.62 486.4,964.37 v1(489.62,964.37)
PMOD_B3_N: J31.10 U11.12 | length 552.1
  Top Layer w8.75: v1(459.58,1039.28) 461.35,1037.51 468.64,1037.51 471.49,1034.65 495.1,1034.65 ; 495.13,1034.62 542.66,1034.62 548.04,1040 U11.12@577,1040
  L3-SIG w5.5: J31.10@270,865 270,823.97 273.22,820.75 410.4,820.75 423.08,833.43 423.08,1017.95 438.16,1033.03 450.11,1033.03 456.36,1039.28 v1(459.58,1039.28)
PMOD_B3_P: J31.9 U11.13 | length 552.1
  Top Layer w8.75: v1(459.58,1015.28) 461.35,1017.05 468.64,1017.05 471.49,1019.9 488.99,1019.9 ; 489.02,1019.88 542.66,1019.88 548.04,1014.5 U11.13@577,1014.5
  L3-SIG w5.5: J31.9@270,765 270,806.03 273.22,809.25 415.16,809.25 434.58,828.67 434.58,1013.18 442.92,1021.53 450.11,1021.53 456.36,1015.28 v1(459.58,1015.28)
PS_DONE: P1.113 R68.2 | length 2267.7
  Top Layer w8: R68.2@1183,161 1228,116 1548,116 1569,137 1569,164 1472,261 1472,461 1397,536 1069,536 1028.99,576.01 1028.99,904.99 1273,1149 1273,1284 1326.27,1337.27 1369.27,1337.27 1383.35,1351.35 P1.113@1383.35,1403.61
PS_JTAG_TCK: P1.114 R56.1 U9.10 | length 3701.5
  Top Layer w8: R56.1@955,1913 v1(1186,1913) 1298,1913 1344.83,1866.17 v1(1344.83,1754.17) ; P1.114@1383.19,1250.65 v1@1383.19,1309.9 ; v1@3089.03,1395 U9.10@3191,1395
  Bottom Layer w8: v1(1186,1913) 1260,1987 1260,2137 1463,2340 2144.03,2340 v1(3088.89,1395.13) ; v1(1344.83,1754.17) 1344.83,1436.45 1383.07,1398.21 1383.07,1310.01 v1(1383.11,1309.97)
PS_JTAG_TDI: P1.116 R58.1 U9.12 | length 3712.7
  Top Layer w8: R58.1@955,1757 959,1753 v1(1128,1753) 1151,1730 v1(1291,1730) ; P1.116@1363.66,1230.39 v1@1363.66,1289.63 ; v1@3089.03,1080 U9.12@3191,1080
  Bottom Layer w8: v1(1128,1753) 1578,2203 2173.49,2203 3052.22,1324.28 3052.22,1116.81 v1(3088.89,1080.13) ; v1(1291,1730) 1291,1457.79 1363.59,1385.2 v1(1363.59,1289.7)
PS_JTAG_TDO: P1.118 R57.1 U9.11 | length 3660.6
  Top Layer w8: R57.1@955,1835 960,1840 v1(1155,1840) 1233,1762 v1(1269,1762) ; P1.118@1344.03,1250.65 v1@1344.03,1309.9 ; v1@3089.03,1238 U9.11@3191,1238
  Bottom Layer w8: v1(1155,1840) 1288,1973 1288,2078 1482,2272 2166.59,2272 3088.89,1349.69 v1(3088.89,1238.13) ; v1(1269,1762) 1269,1434.45 1343.96,1359.49 v1(1343.96,1309.97)
PS_JTAG_TMS: P1.120 R55.1 U9.13 | length 3799.7
  Top Layer w8: R55.1@955,1992 v1(982,1992) ; P1.120@1324.29,1230.39 v1@1324.29,1289.63 ; v1(3088.89,922.13) 3089.03,922 U9.13@3191,922
  Bottom Layer w8: v1(982,1992) 1056,1918 1056,1753 1098,1711 1133,1711 ; v1(1324.22,1289.7) 1216.22,1397.7 1216.22,1627.78 1133,1711 ; v1(3088.89,922.13) 3088.89,999.59 3009.84,1078.64 3009.84,1287.09 2358.97,1937.97 2129.03,1937.97 1998,2069 1491,2069 1133,1711
PS_SRST_N: P1.115 R59.1 R60.1 R61.2 U9.9 | length 3921.2
  Top Layer w8: R60.1@883,479 R61.2@923,479 923,482.87 998.78,558.65 998.78,950.86 1034,986.08 1034,1599 ; R59.1@955,1599 1034,1599 ; P1.115@1363.66,1403.61 1363.83,1403.78 1363.83,1599 1034,1599 ; 1363.83,1599.01 1375.82,1611 1582.29,1611 1601.29,1630 v1(1604,1630) ; U9.9@3347,1497 v1@3347,1598.97
  L6-SIG w8: v1(1604,1630) 1634.89,1599.11 v1(3347.13,1599.11)
PWR_GOOD: P1.117 R70.2 | length 1815.5
  Top Layer w8: P1.117@1343.98,1403.61 1343.98,1358.27 1338.06,1352.36 1311.36,1352.36 1257,1298 1257,1162.98 1014.99,920.97 1014.99,541.43 1052.42,504 1400,504 1446.94,457.06 1446.94,247.06 R70.2@1535,159
RF_CLK0_N: R19.2 R20.2 R24.1 U4.12 | length 145.7
  Top Layer w8.75: U4.12@486.04,3074.81 487.66,3073.19 501.91,3073.19 502.91,3072.19 515.29,3072.19 520.41,3077.31 520.41,3079.19 526.04,3084.81 531.66,3079.19 531.66,3077.31 536.79,3072.19 553.29,3072.19 558.41,3077.31 558.41,3079.19 564.04,3084.81 569.66,3079.19 569.66,3077.31 574.79,3072.19 588.29,3072.19 593.41,3077.31 593.41,3079.19 R20.2@599.04,3084.81
RF_CLK0_P: R18.2 R21.2 R23.1 U4.11 | length 145.7
  Top Layer w8.75: U4.11@486.04,3054.81 487.66,3056.44 501.91,3056.44 502.91,3057.44 515.29,3057.44 520.41,3052.31 520.41,3050.44 526.04,3044.81 531.66,3050.44 531.66,3052.31 536.79,3057.44 553.29,3057.44 558.41,3052.31 558.41,3050.44 564.04,3044.81 569.66,3050.44 569.66,3052.31 574.79,3057.44 588.29,3057.44 593.42,3052.31 593.42,3050.44 R21.2@599.04,3044.81
RF_CLK_N: P2.03 R20.1 | length 729.7
  Top Layer w8.75: R20.1@639,3084 644.62,3078.38 644.62,3076.5 649.75,3071.37 662.12,3071.37 892.48,3071.38 947.75,3016.11 947.75,2857.25 1035.14,2769.86 1097.04,2769.86 1098.88,2771.7 1142.76,2771.7 P2.03@1143.39,2772.32
RF_CLK_P: P2.05 R21.1 | length 729.7
  Top Layer w8.75: R21.1@639,3044 644.62,3049.62 644.62,3051.5 649.75,3056.62 668.23,3056.62 886.38,3056.62 933,3010 933,2851.14 1029.04,2755.11 1097.04,2755.11 1098.88,2753.26 1142.76,2753.26 P2.05@1143.39,2752.64
SATA_RX_N: C34.2 J17.5 | length 104.3
  Top Layer w8.75: C34.2@493,386 483.38,376.38 483.38,332.62 501,315 J17.5@501,293
SATA_RX_P: C35.2 J17.6 | length 104.7
  Top Layer w8.75: J17.6@451,293 451,315 468.62,332.62 468.62,375.38 C35.2@458,386
SATA_TX_N: C32.2 J17.3 | length 104.7
  Top Layer w8.75: J17.3@601,293 601,315 618.62,332.62 618.62,374.38 608,385 C32.2@608,386
SATA_TX_P: C31.2 J17.2 | length 104.7
  Top Layer w8.75: C31.2@644,386 644,385 633.38,374.38 633.38,332.62 651,315 J17.2@651,293
UART0_RX: P1.84 U9.6 | length 2435.2
  Top Layer w8: P1.84@1678.62,1230.39 1678.62,1282.92 1700,1304.3 v1(1700,1320) ; U9.6@3819,1497 v1@3819,1598.97
  L6-SIG w8: v1(1700,1320) 1772.51,1392.51 2474.31,1392.51 2494.8,1413 2661,1413 2707,1459 3209,1459 3300,1550 3660,1550 3709.11,1599.11 v1(3819.13,1599.11)
UART0_TX: P1.80 R63.2 U9.5 | length 2689.4
  Top Layer w8: P1.80@1716.99,1231.39 P1.80@1717.99,1230.39 v1@1717.99,1285.01 ; R63.2@3975.5,1583 3975.5,1592 v1(3975.5,1619.38)
  Top Layer w10: U9.5@3975,1395 3975.5,1395.5 R63.2@3975.5,1583
  L6-SIG w8: v1(1718.14,1283.77) 1718.14,1305.01 1780.54,1367.41 2489.59,1367.41 2516.18,1394 2776,1394 2802,1420 3263,1420 3313,1470 3826.12,1470 v1(3975.5,1619.38)
UART1_RX: J23.18 P1.86 | length 463.2
  Top Layer w8: P1.86@1658.94,1230.39 1658.94,1101.06 J23.18@1893,867
  Bottom Layer w8: J23.18@1891,869 J23.18@1893,867
UART1_TX: J23.20 P1.82 | length 534.8
  Top Layer w8: P1.82@1698.31,1230.39 1698.31,1104.69 1874.5,928.5 1931.5,928.5 J23.20@1993,867
  Bottom Layer w8: J23.20@1993,867 J23.20@1993,883
USB3_TX0_N: C42.2 J18.7 TVS1.4 TVS1.7 | length 135.4
  Top Layer w8.75: J18.7@3558.78,27 3555,30.78 3555,60.14 3562.88,68.02 3562.88,140.88 3574,152 C42.2@3574,153
USB3_TX0_P: C41.2 J18.6 TVS1.5 TVS1.6 | length 136.6
  Top Layer w8.75: J18.6@3533.78,27 3540,33.22 3540,66 3548.12,74.12 3548.12,140.88 3537,152 C41.2@3537,153
USB_CPEN: P1.76 R29.2 U5.1 | length 1882.2
  Top Layer w8: v1(1757.01,1169.01) 1757.19,1169.19 1757.19,1230.21 P1.76@1757.36,1230.39
  Top Layer w10: v1(2494,182) 2494,85 2526,53 U5.1@2571,53 R29.2@2571,2
  Bottom Layer w8: v1(1757.01,1169.01) 1726,1169 1702,1145 1702,1079 1766,1015 2078,1015 2141.82,951.18 2215.82,951.18 2244,923 2244,431 v1@2493.5,181.5
USB_ID: JP4.2 P1.78 | length 1150.2
  Top Layer w8: P1.78@1737.68,1230.39 1737.68,1142.86 v1(1749.96,1130.57)
  Bottom Layer w8: v1(1749.96,1130.57) 1749.96,1096.04 1791,1055 2269,1055 2459,865 JP4.2@2665,865
USB_ID_PIN: J18.4 JP4.3 | length 1435.4
  Top Layer w10: JP4.3@2665,765 2813,913 3016,913 3083.5,845.5 3083.5,563.5 3347,300 J18.4@3347,27
USB_JTAG_N: J26.2 U9.16 U12.3 | length 820.9
  Top Layer w8.75: U9.16@3504,663 3505,664 3570.5,664 3574,660.5 3574,505.88 3556,487.88 3542.63,487.88 3537.5,493 v1(3535,493) ; v1@3722,360.41 3774.41,360.41 ; 3774.91,360.41 3786.53,372.03 ; U12.3@3786.5,403 3786.53,372.03 ; J26.2@3953.5,366 3947.88,360.38 3795.12,360.38 3786.53,368.97 3786.53,372.03
  L3-SIG w5.5: v1(3535,493) 3537.72,493 3544.47,486.25 3566.01,486.25 3644.26,408 3649,408 3655,414 3666,414 3671.94,408.06 3671.94,398.81 3665.34,392.21 3665.34,386.92 3693.51,358.75 3710.53,358.75 3717.28,365.5 v1(3720,365.5)
USB_JTAG_P: J26.3 U9.17 U12.4 | length 820.9
  Top Layer w8.75: v1(3535,468) 3537.5,468 3542.63,473.12 3562.11,473.12 3588.75,499.77 3588.75,659.75 3593,664 3661,664 U9.17@3662,663 ; v1@3722,345.66 3774.34,345.66 ; 3774.84,345.66 3786.53,333.97 ; U12.4@3786.5,303 3786.53,333.97 ; J26.3@3953.5,340 3947.87,345.63 3796.13,345.63 3786.53,336.03 3786.53,333.97
  L3-SIG w5.5: v1(3535,468) 3537.72,468 3544.47,474.75 3561.25,474.75 3688.75,347.25 3710.53,347.25 3717.28,340.5 v1(3720,340.5)
USB_N: J18.2 P1.38 TVS2.1 | length 2305.1
  Top Layer w8.75: P1.38@2131.38,1230.39 2131.38,1195.39 2128.23,1192.24 2128.23,1098.85 2133.36,1093.72 v1(2133.36,1091.22) ; TVS2.1@3294,111 3296.12,108.88 3296.12,100.62 3300.62,96.12 3300.62,78.62 v1(3296,74) ; J18.2@3295,27 3300.62,32.62 v1@3300.62,72.38
  L3-SIG w5.5: v1(2133.36,1091.22) 2133.36,1088.5 2126.61,1081.75 2126.61,1034.91 2140.41,1021.11 2259.66,1021.11 2489,791.76 2489,285.47 2782.27,-7.81 3083.19,-7.81 3087.54,-3.46 3087.54,10.54 3093,16 3114,16 3117.26,12.74 3117.26,-2.26 3122.81,-7.81 3283.19,-7.81 3302.25,11.25 3302.25,64.53 3296,70.78 v1(3296,74)
USB_P: J18.3 P1.40 TVS2.2 | length 2305.5
  Top Layer w8.75: v1(2108.36,1091.22) 2108.36,1093.72 2113.48,1098.85 2113.48,1189.78 2112.32,1190.95 2112.32,1229.76 P1.40@2111.69,1230.39 ; v1@3315.38,71.88 3315.38,32.62 J18.3@3321,27 ; v1(3320,74) 3315.38,78.62 3315.38,96.12 3319.88,100.62 3319.88,108.88 TVS2.2@3322,111
  L3-SIG w5.5: v1(2108.36,1091.22) 2108.36,1088.5 2115.11,1081.75 2115.11,1030.15 2135.65,1009.61 2254.89,1009.61 2477.5,787 2477.5,280.7 2777.51,-19.31 3287.96,-19.31 3313.75,6.49 3313.75,64.53 3320,70.78 v1(3320,74)
USB_VBUS: JP3.2 P1.74 | length 1700
  Top Layer w8: v1(1776.94,1149.03) 1776.94,1230.28 P1.74@1777.05,1230.39
  Bottom Layer w8: v1@1777,1151 1776.01,1150.01 1737.01,1150.01 1722,1135 1722,1091 1779,1034 2250,1034 2869,415 JP3.2@2955,415
VBUS: C39.1 JP1.2 JP2.2 L9.1 R27.1 R28.2 | length 1255.7
  Top Layer w15: JP1.2@2665,415 2800,415 ; JP2.2@2955,865 2850,865 2800,815 2800,415 ; L9.1@2993,49 C39.1@2993,107 R27.1@2905,107 2824,107 2800,131 2800,415
VCC1V8: C4.1 C43.1 C65.1 C68.1 C71.1 C79.1 J23.22 J24.2 L10.1 P1.119 R60.2 U9.8 U10.2 U10.10 U11.2 U11.10 | length 7524.2
  Top Layer w8: J23.22@2093,867 2104,878 2104,914 2142,952 C71.1@2142,953
  Top Layer w12: U11.2@807,861.5 750.5,861.5 749,863 ; U11.10@807,1065.5 749.5,1065.5 749,1066 ; U10.2@807,1231.5 749.5,1231.5 749,1232 ; J24.2@829,2071 v1(930,2071) ; v1(875,1475) 835,1435 807.5,1435 U10.10@807,1435.5 806.23,1434.73 762.73,1434.73 749,1421 749,1232 ; R60.2@883,439 840.5,439 749,530.5 C65.1@749,788 749,863 ; v1(1324.11,1499.92) 1324.11,1403.8 P1.119@1324.29,1403.61 ; L10.1@2175,2074 C43.1@2224,2074 v1(2224,2049) 2317,1956 2386,1956 2685,1657 3363,1657 3426,1594 C79.1@3504,1594 ; U9.8@3504,1497 3504,1592 C79.1@3506,1594 ; 749,863 749,1066 ; 749,1066 C68.1@749,1156 749,1232
  L5-PWR w12: v1(875,1475) 896.96,1453.04 1277.23,1453.04 v1(1324.11,1499.92)
  L5-PWR w20: J23.22@2093,867 2093,938 2050,981 1143,981 1000.72,1123.28 856.72,1123.28 795,1185 795,1395 v1(875,1475) 875,2016 v1(930,2071) 2202,2071 v1(2224,2049)
VCC3V3: C1.1 C51.1 C66.2 C67.1 C69.2 C70.1 C72.1 C75.1 C76.1 C78.1 J19.4 J21.14 J21.16 J23.25 J23.26 J28.6 J28.12 J31.6 J31.12 JP4.1 LED1.2 P2.21 R29.1 R33.1 R34.1 R35.1 R36.1 R41.2 R48.1 R63.1 R65.1 R69.1 U9.2 U9.15 U10.19 U11.19 U13.2 | length 4864.5
  Top Layer w12: J28.12@270,1965 J28.6@370,1965 C67.1@465,1965 v1(465,2003) ; J31.6@370,1065 426,1065 517,1156 v1(601,1156) C69.2@635,1156 ; U11.19@577.77,860.73 635,860.73 ; U10.19@577.77,1230.73 620.27,1230.73 635,1216 C69.2@635,1156 ; v1(600,788) C66.2@635,788 635,860.73 ; R65.1@943,41 v1(943,69) ; v1(1022.84,2595) C1.1@1052,2595 ; C1.1@1053,2595 1053.08,2595.08 1143.31,2595.08 P2.21@1143.39,2595.16 ; R69.1@1289,42 v1(1289,70) ; v1(1587.57,351.27) 1587.57,323.43 C51.1@1588,323 R36.1@1588,287 ; J19.4@1936,-61 v1(1936,6) ; R33.1@2031,1819 R34.1@2031,1855 v1(2031,1878) ; R35.1@2051,513 v1(2093,513) ; J23.25@2293,767 J23.26@2293,867 C72.1@2372,867 ; v1@2544,-38 R29.1@2571,-38 2575,-34 2617,-34 LED1.2@2621,-30 ; v1(3209,1980) R48.1@3237,1980 ; U9.15@3347,663 3347.18,662.82 C75.1@3347.18,571.03 ; C75.1@3347.21,571 v1(3375,571) ; R41.2@3355,1909 v1(3385,1909) ; U9.2@3975,922 C78.1@4061,922 4061,962.62 4065,966.62 4065,1535.5 R63.1@4015.5,1585 ; 635,860.73 C69.2@635,1156
  Top Layer w20: J31.12@270,1065 J31.6@370,1065 369.88,1065.12 369.88,1165.63 C70.1@369.76,1165.63
  Top Layer w40: U13.2@2457,2949 U13.2@2457,3189
  L5-PWR w15: v1(465,2003) 515,2053 515,2447 679,2611 1006.84,2611 v1(1022.84,2595)
  L5-PWR w20: v2(3440,915) 3441,914 3718,914 3765,961 v1(4061,961)
  other v1: 2542,-38 2568,3171 2593,3171 2568,3191 2593,3191
VCC3V3_DP: C56.1 C57.1 C60.1 C84.1 C85.1 J20.20 R71.2 U7.14 U8.5 U15.1 U15.2 | length 1129.8
  Top Layer w8: U8.5@3536,2022 U8.5@3537,2021 ; J20.20@3665.44,2056.3 J20.20@3666.22,2056.3
  Top Layer w12: C85.1@3057,2115 R71.2@3057,2154 3100,2154 3101,2155 v1(3119,2155) 3427.63,2155 3469.63,2113 C60.1@3491,2113 ; v1(3119,2038) 3120.15,2036.85 3120.15,2026.85 3124,2023 C57.1@3124,2002 U7.14@3124,1940 ; v1(3525,2113) C60.1@3491,2113 ; U8.5@3536,2022 3511,2022 3491,2042 C60.1@3491,2113 ; C56.1@3586,2098 3609,2075 3646.74,2075 J20.20@3665.44,2056.3
  L5-PWR w12: v1(3119,2038) v1(3119,2155) ; v1(3525,2113) 3555,2083 3639.52,2083 J20.20@3666.22,2056.3
VCC4V8_LNA0: C5.1 C87.1 C88.1 L1.1 R73.2 U16.1 U16.2 | length 559.8
  Top Layer w12: v1(1905,3711) C5.1@1905,3752 L1.1@1956,3752
  L5-PWR w16: v1(1905,3711) 1937,3679 1937,3415 v1(2001,3351)
  Bottom Layer w15: C88.1@1960,3285 R73.2@2001,3285 ; C87.1@2001,3324 v1(2001,3351)
VCC4V8_LNA1: C18.1 C90.1 C91.1 L7.1 R75.2 U17.1 U17.2 | length 746.4
  Top Layer w12: L7.1@1735,3791 C18.1@1784,3791 v1(1828,3791)
  L5-PWR w16: v1(1746,3353) 1851,3353 1887,3389 1887,3629 1851,3665 1851,3768 v1(1828,3791)
  Bottom Layer w15: C91.1@1708,3283 R75.2@1748,3283 ; C90.1@1746,3322 v1(1746,3353)
VCC5V0: C2.1 C3.1 C33.1 C77.1 C80.1 C83.1 C86.1 C89.1 C104.1 J1.2 JP1.3 P2.29 P2.30 P2.31 P2.32 P2.33 P2.34 P2.35 P2.36 P2.37 P2.38 P2.39 P2.40 R77.1 R81.2 U5.7 U13.3 U14.7 U14.8 U14.9 U15.7 U15.8 U15.9 U16.7 U16.8 U16.9 U17.7 U17.8 U17.9 | length 8916.4
  Top Layer w8: C3.1@1045,2496.37 1045.37,2496.73 P2.31@1143.39,2496.73 ; P2.38@1316.61,2437.68 1316.78,2437.84 1397.84,2437.84 C2.1@1398,2438
  Top Layer w10: U14.9@564,3336 574,3346 U14.7@619,3346 ; C83.1@2852,2161 2852,2159 C83.1@2857,2154 ; U15.7@2894,2174 2939,2174 U15.9@2949,2184 2949,2178 U15.9@2925,2154
  Top Layer w12: v1(2299,78) C33.1@2333,78 U5.7@2391,78
  Top Layer w15: U14.9@583,3366 U14.8@619,3366 C80.1@670,3366 ; C80.1@670,3355 C80.1@670,3366 ; v1(670,3393.55) C80.1@670,3366 ; v1(2852,2124) C83.1@2852,2159
  Top Layer w20: U14.9@564,3336 564,3347 U14.9@583,3366
  Top Layer w50: J1.2@820,2425 C104.1@1019.94,2425 ; C104.1@1019.97,2424.97 1129,2424.97 1144,2439.97 P2.35@1144,2457.36
  L5-PWR w12: 2259,2714 2262,2714
  L5-PWR w20: 2262,2714 v1(2852,2124) ; v1(2299,78) 2516.02,78 2665,226.97 JP1.3@2665,315
  L5-PWR w25: v1(670,3393.55) 1243.82,3393.55 1619.37,3018 v1(1751,3018) v1(2003,3018) 2425,3018 2494,2949
  L5-PWR w100: v2@1388,2473 1422,2473 2018,2473 2259,2714 2494,2949 v2(2739,2949)
  Bottom Layer w20: C89.1@1750,3077 1751,3077 v1(1751,3018) ; v1(2003,3018) 2003,3077 C86.1@2004,3077 ; v1(2299,78) 2362,141 3013,141 3148,276 3148,1452 2852,1748 v1(2852,2124)
  other v1: 2949,2159 2949.32,2208.65 1422,2503 1741,3176 1790.65,3175.68 1995,3176 2044.65,3175.68 564,3311 564.32,3360.65
  other v2: 1371,2476 1396,2476 1422,2476 1371,2503 1396,2503 2714,2924 2739,2924 2764,2924 2764,2949 2714,2975 2739,2975 2764,2975
VCC_RFCLK: C23.1 C24.1 C27.1 C28.1 C81.1 C82.1 R6.1 R7.1 R18.1 R19.1 R66.2 U3.8 U3.13 U4.8 U4.13 U14.1 U14.2 | length 1958.9
  Top Layer w8: R66.2@458,3366 U14.1@509,3366 ; R19.1@564.04,3124.81 R19.1@564.2,3124.98
  Top Layer w10: U14.2@509,3346 U14.1@509,3366 ; U3.8@557,3587 C24.1@557,3541 v1(624,3541) R6.1@624,3605 ; U3.13@557,3703 557,3750 v1(624,3750) R7.1@624,3725
  Top Layer w12: v2(378,3422) C82.1@378,3366 R66.2@458,3366 ; U4.8@458.04,2986.81 458.04,2946.81 v1(564.04,2946.81) R18.1@564.04,3004.81 ; U4.13@458.04,3102.81 458.04,3140.81 482.04,3140.81 492.58,3151.35 v1(564.2,3151.35) R19.1@564.2,3124.98
  L5-PWR w20: v1(564.04,2946.81) 564.04,3151.19 v1(564.2,3151.35) 378,3337.56 v2(378,3422) 505,3422 v1(624,3541) v1(624,3750)
pads on no net: "J4. " "J6. " "J8. " "J10. " "J12. " "J14. " "P2. " J1.3 J20. J20.10 J20.12 J20.15 J20.17 J21. J21.15 J24.12 J24.MH1 J24.MH2 P2. U3.6 U3.7 U3.9 U3.10 U3.14 U3.15 U4.6 U4.7 U4.9 U4.10 U4.14 U4.15 U5.4 U6.1 U6.2 U6.3 U6.4 U6.6 U6.7 U6.24 U7.3 U7.5 U7.6 U7.13 U8.1 U9.3 U9.4 U12.1 U14.4 U15.4 U16.4 U17.4

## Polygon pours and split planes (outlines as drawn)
GND on L5-PWR "L5-GND" (solid, pour order 2): -135,-135 -135,4115 4115,4115 4115,2122 3829,2122 3829,1778 4115,1778 4115,-135
VCC3V3 on L5-PWR "L5-3V3" (solid, pour order 0): 415,499 924,-10 1865,-10 1925,-70 2830,-70 3482,582 3482,2055.09 3993,2400.71 3993,2998 3692.03,3298.97 2490,3298.97 2490,3084 2809,3084 2852,3041 2852,2250 2751,2149 1445,2149 480,2149 415,2084
GND on L2-GND "L2-GND" (solid, pour order 5): -135,-135 -135,4115 4115,4115 4115,2122 3829,2122 3829,1778 4115,1778 4115,-135
GND on Bottom Layer "Bottom-GND" (solid, remove dead copper, pour order 10): -135,-135 -135,4115 4115,4115 4115,2122 3829,2122 3829,1778 4115,1778 4115,-135
GND on Top Layer "Top Layer-GND" (solid, remove dead copper, pour order 11): -135,-135 -135,4115 4115,4115 4115,2122 3829,2122 3829,1778 4115,1778 4115,-135
NetC73_2 on Top Layer "Bottom - GND" (solid, remove dead copper, pour order 4): 3502,3272 3730,3272 3730,3382 3701,3411 3450.27,3411 3450.27,3397 3490.6,3380.4 3502,3369
GND on L7-GND "L7-GND" (solid, remove dead copper, pour order 9): -135,-135 -135,4115 4115,4115 4115,2122 3829,2122 3829,1778 4115,1778 4115,-135
GND on L3-SIG "L3-GND" (solid, pour order 6): -135,-135 -135,4115 4115,4115 4115,2122 3829,2122 3829,1778 4115,1778 4115,-135
GND on L6-SIG "L6-GND" (solid, remove dead copper, pour order 7): -135,-135 -135,4115 4115,4115 4115,2122 3829,2122 3829,1778 4115,1778 4115,-135
GND on L4-GND "L4-GND" (solid, remove dead copper, pour order 8): -135,-135 -135,4115 4115,4115 4115,2122 3829,2122 3829,1778 4115,1778 4115,-135

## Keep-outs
Top Layer:
  the board outline again, w10
L4-GND:
  the board outline again, w10
L3-SIG:
  the board outline again, w10
L5-PWR:
  the board outline again, w10
L6-SIG:
  the board outline again, w10
L2-GND:
  the board outline again, w10
L7-GND:
  the board outline again, w10
Bottom Layer:
  the board outline again, w10

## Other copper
Top Layer:
  rectangle net GND: 619,3282 697,3326
  rectangle net GND: 2171,3751 2232,3779
  rectangle net GND: 1596,3751 1657,3779
  region net VCC5V0: 671,3371 571,3371 571,3341 671,3341
  region net VCC_RFCLK: 523,3371 446,3371 446,3345 523,3345
  rectangle net VCC3V3_DP: 2990,2149 3067,2175
  rectangle net VCC5V0: 2842,2149 2942,2179
  rectangle net VCC5V0: 1108,2416 1441,2517
  region net VCC3V3: 2458,3217 2472,3231 2599,3231 2612,3218 2612,3158 2601,3147 2472,3147 2458,3161
  region net VCC5V0: 2832,3067 2832,2939 2796,2903 2525,2903 2525,2991 2711,2991 2787,3067
  text ".Layer_Name" at 2837.03,-378.88 h75
L4-GND:
  text ".Layer_Name" at 2837.03,-378.88 h75
L3-SIG:
  text ".Layer_Name" at 2837.03,-378.88 h75
L5-PWR:
  text ".Layer_Name" at 2837.03,-378.88 h75
L6-SIG:
  text ".Layer_Name" at 2837.03,-378.88 h75
L2-GND:
  text ".Layer_Name" at 2837.03,-378.88 h75
L7-GND:
  text ".Layer_Name" at 2837.03,-378.88 h75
